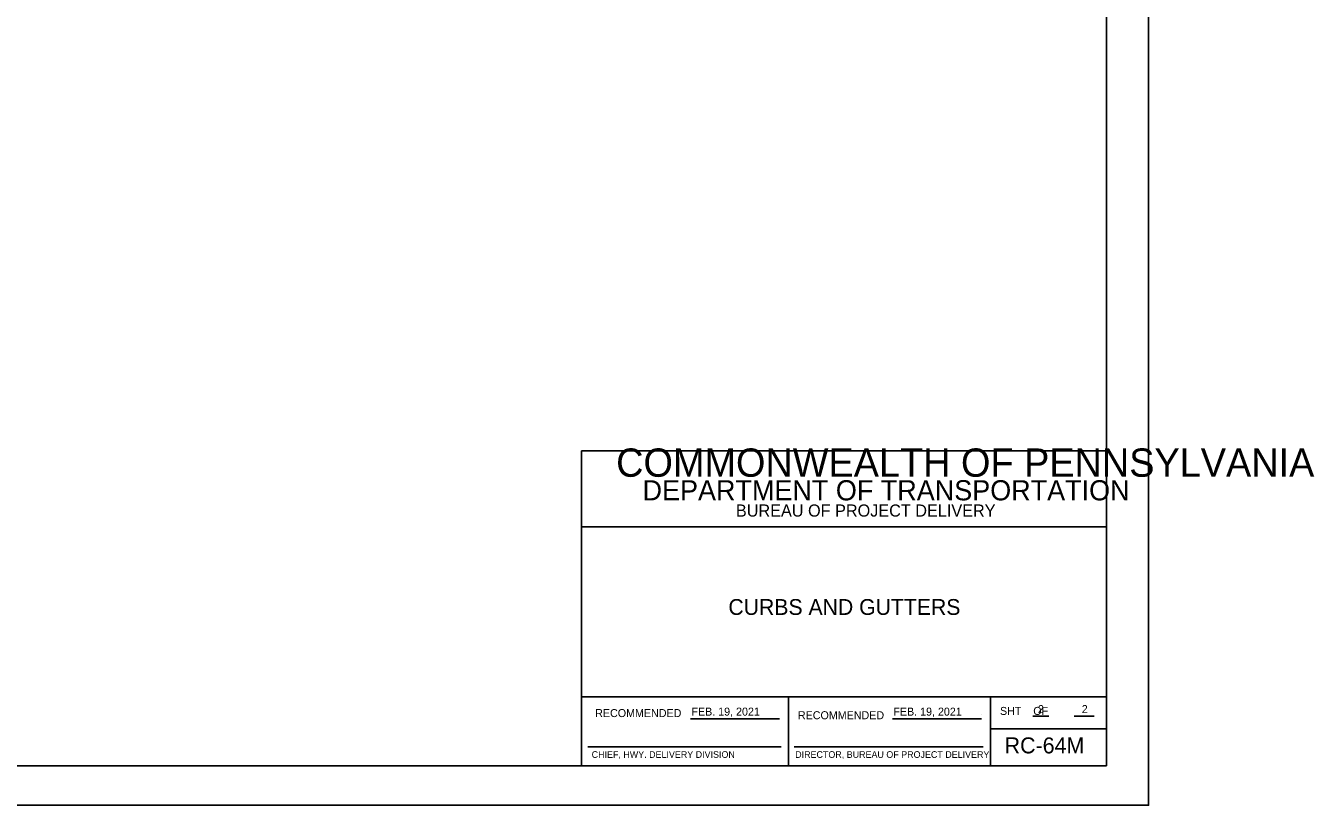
# Model space of a CAD drawing. Extents: x 2092490 to 2102560, y 980575 to 982524.
# Drawn here: x 2100949 to 2102560, y 980575 to 981549 of the extents above; entities that cross this region are included whole.
import ezdxf

# ---------------------------------------------------------------- set-up
doc = ezdxf.new("R2010")
doc.units = 0
doc.layers.add('1', color=7, linetype='Continuous')
doc.layers.add('PLT-BNDY', color=7, linetype='Continuous')

msp = doc.modelspace()

# ---------------------------------------------------------------- linework, layer by layer
at = {"layer": '1'}
for p, q in [((2102300, 980624.1), (2102300, 982474.5)), ((2102300, 981017.8), (2101643.8, 981017.8)), ((2101643.8, 981017.8), (2101643.8, 980624.1)), ((2102300, 980922.8), (2102300, 981017.8)), ((2101643.8, 980710.6), (2101643.8, 980922.8)), ((2101643.8, 980922.8), (2102300, 980922.8)), ((2102300, 980710.6), (2101643.8, 980710.6)), ((2101902.3, 980624.1), (2101902.3, 980710.6)), ((2101902.3, 980710.6), (2101902.3, 980624.1)), ((2102155, 980624.1), (2102155, 980710.6)), ((2102155, 980710.6), (2102155, 980670.2)), ((2102300, 980624.1), (2102300, 980710.6)), ((2101779.8, 980683.1), (2101891, 980683.1)), ((2102032.5, 980683.1), (2102143.6, 980683.1)), ((2102144.2, 980688.6), (2102144.2, 980688.6)), ((2102207.7, 980686.3), (2102227.8, 980686.3)), ((2102259.5, 980686.3), (2102284.6, 980686.3)), ((2102155, 980670.2), (2102300, 980670.2)), ((2101651.7, 980648.1), (2101893.2, 980648.1)), ((2101909.3, 980648.1), (2102145.8, 980648.1)), ((2099721.2, 980624.1), (2102300, 980624.1)), ((2101643.8, 980624.1), (2101902.3, 980624.1)), ((2101902.3, 980624.1), (2102155, 980624.1))]:
    msp.add_line(p, q, dxfattribs=at)
at = {"layer": 'PLT-BNDY'}
msp.add_lwpolyline([(2099593.3, 982523.7), (2102352.5, 982523.7), (2102352.5, 980574.9), (2099593.3, 980574.9)], close=True, dxfattribs=at)

# ---------------------------------------------------------------- texts
at = {"layer": '1'}
for s, height, p in [('COMMONWEALTH OF PENNSYLVANIA', 35.379, (2101687, 980985.5)), ('DEPARTMENT OF TRANSPORTATION', 25.211, (2101720, 980956)), ('BUREAU OF PROJECT DELIVERY', 15.164, (2101836.7, 980935.7)), ('CURBS AND GUTTERS', 19.816, (2101827.3, 980812.8)), ('2', 10, (2102214.2, 980690.1)), ('2', 10, (2102269, 980690.1)), ('RECOMMENDED', 10, (2101660.8, 980685.1)), ('FEB. 19, 2021', 10, (2101781.1, 980686.9)), ('RECOMMENDED', 10, (2101914.2, 980682.4)), ('FEB. 19, 2021', 10, (2102033.5, 980686.9)), ('SHT    OF', 10, (2102166.8, 980687.8)), ('RC-64M', 20, (2102172.6, 980639.7)), ('CHIEF, HWY. DELIVERY DIVISION', 8.333, (2101656.4, 980634.1))]:
    msp.add_text(s, height=height, dxfattribs=at).set_placement(p)
msp.add_text('DIRECTOR, BUREAU OF PROJECT DELIVERY', height=8.333, rotation=360, dxfattribs=at).set_placement((2101910.8, 980634.1))

doc.saveas('drawing.dxf')
